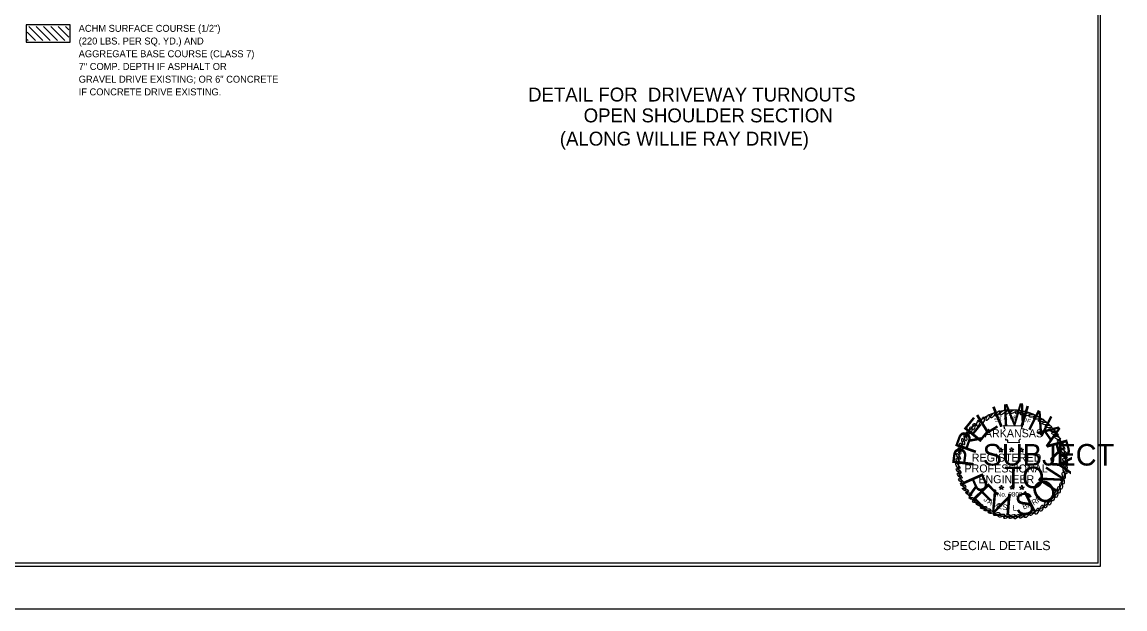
# Model space of a CAD drawing. Extents: x 714919 to 718439, y 1619644 to 1621844.
# Drawn here: x 716536 to 718439, y 1619644 to 1620657 of the extents above; entities that cross this region are included whole.
import ezdxf

# ---------------------------------------------------------------- set-up
doc = ezdxf.new("R2010")
doc.units = 0
for name, color, linetype in [('Default', 7, 'Continuous'), ('R_Border', 7, 'Continuous'), ('R_Border Notes', 7, 'Continuous'), ('R_Border PE', 7, 'Continuous'), ('R_Border Prem', 7, 'Continuous'), ('R_No Plot', 7, 'Continuous')]:
    doc.layers.add(name, color=color, linetype=linetype)

msp = doc.modelspace()

# ---------------------------------------------------------------- linework, layer by layer
at = {"layer": 'Default'}
msp.add_lwpolyline([(716543.2, 1620652), (716543.2, 1620622.1), (716619.4, 1620622.1), (716619.4, 1620652)], close=True, dxfattribs=at)
for points in [[(716545, 1620639.2), (716559.4, 1620624.9)], [(716547.7, 1620649.2), (716572.1, 1620624.9)], [(716560.4, 1620649.2), (716584.7, 1620624.9)], [(716573, 1620649.2), (716597.4, 1620624.9)], [(716585.7, 1620649.2), (716610.1, 1620624.9)], [(716598.4, 1620649.2), (716617, 1620630.6)], [(716611, 1620649.2), (716617, 1620643.3)], [(716545, 1620626.5), (716546.7, 1620624.9)]]:
    msp.add_lwpolyline(points, dxfattribs=at)
at = {"layer": 'R_Border'}
for p, q in [((718393.2, 1619722.5), (718393.1, 1621777.1)), ((718393.2, 1619722.5), (715231.2, 1619722.5)), ((714919.1, 1619643.5), (718439.3, 1619643.8))]:
    msp.add_line(p, q, dxfattribs=at)
at = {"layer": 'R_Border PE'}
for points in [[(718232.2, 1619953.8), (718230.1, 1619960.3), (718262.7, 1619959.4), (718260.3, 1619955), (718265.3, 1619954.7), (718265, 1619954.1)], [(718258.8, 1619937.5), (718256.1, 1619934.6), (718256.7, 1619930.1), (718237.2, 1619930.7), (718237.2, 1619934.9), (718233.7, 1619934.9), (718233.7, 1619937.5)]]:
    msp.add_lwpolyline(points, dxfattribs=at)
for points in [[(718225.4, 1619921.8), (718226.3, 1619918.9), (718229.2, 1619918.9), (718226.8, 1619917.4), (718227.7, 1619914.4), (718225.4, 1619916.2), (718223, 1619914.4), (718223.9, 1619917.4), (718221.5, 1619918.9), (718224.5, 1619918.9)], [(718243.7, 1619922.1), (718244.6, 1619919.5), (718247.3, 1619919.5), (718245.2, 1619917.7), (718246.1, 1619915), (718243.7, 1619916.5), (718241.3, 1619915), (718242.2, 1619917.7), (718239.9, 1619919.5), (718242.8, 1619919.5)], [(718260.6, 1619921.8), (718261.5, 1619918.9), (718264.4, 1619918.9), (718262.1, 1619917.4), (718263, 1619914.4), (718260.6, 1619916.2), (718258.2, 1619914.4), (718259.1, 1619917.4), (718256.7, 1619918.9), (718259.7, 1619918.9)], [(718226.3, 1619857), (718227.1, 1619854), (718230.1, 1619854), (718227.7, 1619852.6), (718228.6, 1619849.6), (718226.3, 1619851.4), (718223.9, 1619849.6), (718224.8, 1619852.6), (718222.4, 1619854), (718225.4, 1619854)], [(718244.6, 1619857.3), (718245.5, 1619854.6), (718248.2, 1619854.6), (718245.8, 1619852.9), (718247, 1619850.2), (718244.6, 1619851.7), (718242.2, 1619850.2), (718243.1, 1619852.9), (718240.8, 1619854.6), (718243.7, 1619854.6)], [(718261.5, 1619857), (718262.4, 1619854), (718265.3, 1619854), (718263, 1619852.6), (718263.8, 1619849.6), (718261.5, 1619851.4), (718259.1, 1619849.6), (718260, 1619852.6), (718257.6, 1619854), (718260.6, 1619854)]]:
    msp.add_lwpolyline(points, close=True, dxfattribs=at)
for centre, major_axis, ratio in [((718219.6, 1619980.9), (-3.64, -4.4), 0.329518), ((718228.4, 1619982.7), (-4.59, -4.21), 0.348728), ((718236.7, 1619983.2), (-3.87, -3.02), 0.44237), ((718246.4, 1619984.1), (-4.21, -2.45), 0.475469), ((718255.1, 1619983.2), (-4.21, -2.45), 0.475469), ((718186.2, 1619964.6), (-1.53, -5.49), 0.394697), ((718194.1, 1619969.1), (-1.53, -5.49), 0.375751), ((718202.5, 1619974), (-2.46, -5.15), 0.329518), ((718211.5, 1619978), (-3.58, -4.44), 0.329518), ((718263.2, 1619981.7), (-4.21, -2.45), 0.475469), ((718271.2, 1619979.7), (-4.64, -1.48), 0.475469), ((718278.6, 1619976.9), (-4.79, -0.89), 0.475469), ((718286.5, 1619973.3), (-4.85, -0.42), 0.475469), ((718294.8, 1619969), (-4.85, -0.42), 0.475469), ((718168.4, 1619946.2), (0, -5.7), 0.322879), ((718173.1, 1619952.2), (0, -5.7), 0.322879), ((718178.3, 1619958.3), (-1.53, -5.49), 0.391724), ((718301.4, 1619963.9), (-4.87, 0.11), 0.475469), ((718307, 1619958.6), (-5.09, 0.7), 0.451028), ((718313.3, 1619952.2), (-5.17, 1.18), 0.436264), ((718318.5, 1619945.9), (-5.3, 1.59), 0.418512), ((718156.7, 1619924.4), (1.57, -5.48), 0.322879), ((718160.2, 1619932.3), (1.57, -5.48), 0.322879), ((718164, 1619939), (1.57, -5.48), 0.322879), ((718322.8, 1619938.7), (-4.99, 2.77), 0.40589), ((718327.8, 1619930.8), (-4.66, 3.28), 0.40589), ((718151.9, 1619906.9), (3.04, -4.83), 0.322879), ((718153.5, 1619916.3), (1.57, -5.48), 0.322879), ((718330.9, 1619922.8), (-4.3, 3.75), 0.40589), ((718333.5, 1619914.9), (-4.3, 3.75), 0.40589), ((718335.2, 1619907.3), (-4.1, 3.96), 0.40589), ((718150.9, 1619890.4), (3.04, -4.83), 0.322879), ((718151.4, 1619898.8), (3.04, -4.83), 0.322879), ((718336.1, 1619898.9), (-3.5, 4.5), 0.40589), ((718336.3, 1619890.7), (-2.77, 4.99), 0.40589), ((718152.3, 1619881.7), (3.92, -4.14), 0.322879), ((718154.2, 1619873.4), (3.92, -4.14), 0.322879), ((718333.7, 1619874.3), (-1.48, 5.51), 0.40589), ((718335.8, 1619882.1), (-2.3, 5.22), 0.40589), ((718156.7, 1619864.6), (4.29, -3.76), 0.322879), ((718160.1, 1619857), (4.67, -3.27), 0.322879), ((718164.3, 1619849.4), (5.13, -2.49), 0.322879), ((718325.4, 1619849.4), (-0.33, 5.69), 0.40589), ((718329.2, 1619856.2), (-0.33, 5.69), 0.40589), ((718331.9, 1619864.8), (-1.02, 5.61), 0.40589), ((718169.6, 1619842.1), (5.13, -2.49), 0.322879), ((718175.6, 1619834.4), (5.58, -1.19), 0.322879), ((718309.7, 1619828.6), (0.91, 5.63), 0.40589), ((718315.2, 1619835.6), (0.91, 5.63), 0.40589), ((718320.9, 1619841.8), (0.27, 5.7), 0.40589), ((718181.3, 1619828.6), (5.58, -1.19), 0.322879), ((718188.3, 1619823.6), (5.58, -1.19), 0.322879), ((718195.1, 1619818.5), (5.68, 0.48), 0.322879), ((718201.8, 1619814.6), (5.68, 0.48), 0.322879), ((718279, 1619809.5), (3.39, 4.59), 0.40589), ((718287.4, 1619812.2), (2.43, 5.16), 0.40589), ((718295.4, 1619817.3), (2.26, 5.24), 0.40589), ((718302.8, 1619823.7), (1.36, 5.54), 0.40589), ((718209, 1619810.8), (5.68, 0.48), 0.40589), ((718218, 1619807.3), (5.5, 1.52), 0.40589), ((718226.3, 1619804.7), (5.5, 1.52), 0.40589), ((718235.5, 1619803.3), (4.91, 2.91), 0.40589), ((718244.7, 1619803.2), (4.91, 2.91), 0.40589), ((718252.8, 1619803.1), (4.63, 3.33), 0.40589), ((718261.9, 1619804.4), (4.36, 3.68), 0.40589), ((718270.3, 1619805.7), (4.08, 3.98), 0.40589)]:
    msp.add_ellipse(centre, major_axis=major_axis, ratio=ratio, dxfattribs=at)
at = {"layer": 'R_Border Prem'}
msp.add_circle((718244.5, 1619894.9), 92.6, dxfattribs=at)
at = {"layer": 'R_No Plot'}
msp.add_lwpolyline([(715227.2, 1619717.3), (718397.1, 1619717.4), (718397.2, 1621782.5), (715227.1, 1621782.3)], close=True, dxfattribs=at)

# ---------------------------------------------------------------- texts
at = {"layer": 'Default'}
for s, height, p in [('ACHM SURFACE COURSE (1/2") ', 12, (716634, 1620639.9)), ('(220 LBS. PER SQ. YD.) AND ', 12, (716634, 1620618)), ('AGGREGATE BASE COURSE (CLASS 7)', 12, (716634, 1620596)), ('7" COMP. DEPTH IF ASPHALT OR', 12, (716634, 1620574.1)), ('GRAVEL DRIVE EXISTING; OR 6" CONCRETE', 12, (716634, 1620552.1)), ('IF CONCRETE DRIVE EXISTING.', 12, (716634, 1620530.2)), ('DETAIL FOR  DRIVEWAY TURNOUTS', 24, (717409.4, 1620519.6)), ('OPEN SHOULDER SECTION', 24, (717505.3, 1620483.6)), ('(ALONG WILLIE RAY DRIVE)', 24, (717464.2, 1620443.5))]:
    msp.add_text(s, height=height, dxfattribs=at).set_placement(p)
at = {"layer": 'R_Border Notes'}
msp.add_text('SPECIAL DETAILS', height=16, rotation=359.9984, dxfattribs=at).set_placement((718125.4, 1619745.1))
at = {"layer": 'R_Border PE'}
for s, height, rotation, p in [('S', 6.91, 19.5814, (718215.3, 1619965.6)), ('T', 6.91, 14.9614, (718222.7, 1619968)), ('A', 6.91, 5.7216, (718230.1, 1619969.8)), ('T', 6.91, 1.1017, (718238.4, 1619970.4)), ('E', 6.91, 356.4818, (718246.4, 1619970.4)), ('O', 6.91, 342.6221, (718261.8, 1619968.3)), ('F', 6.91, 338.0022, (718269.5, 1619965.9)), ('ARKANSAS', 13.81, 360, (718197.5, 1619939.9)), ('REGISTERED', 13.81, 360, (718175, 1619897.9)), ('PROFESSIONAL', 13.814, 360, (718162.3, 1619879.2)), ('ENGINEER', 13.81, 360, (718186.3, 1619860.6)), ('J', 9.6, 322.4167, (718194.5, 1619831.2)), ('No. 9808', 7.89, 360, (718218.1, 1619837.5)), ('R', 9.6, 29.6215, (718281.7, 1619822)), ('R', 9.6, 35.2219, (718289.6, 1619826.8)), ('A', 9.6, 328.0171, (718201, 1619826.4)), ('M', 9.6, 333.6175, (718209.3, 1619821.6)), ('E', 9.6, 344.8183, (718218.8, 1619817.5)), ('S', 9.6, 350.4187, (718227.2, 1619815.1)), ('L', 9.6, 1.6195, (718245.5, 1619813.2)), ('.', 9.6, 7.2199, (718254.4, 1619813.8)), ('B', 9.6, 18.4207, (718264.1, 1619815.3)), ('A', 9.6, 24.0211, (718272.9, 1619818))]:
    msp.add_text(s, height=height, rotation=rotation, dxfattribs=at).set_placement(p)
at = {"layer": 'R_Border Prem'}
for s, height, rotation, p in [('I', 37.2, 22.0105, (718219.9, 1619955.5)), ('M', 37.2, 2.6943, (718228, 1619959.6)), ('I', 37.2, 343.3781, (718254.3, 1619960.2)), ('N', 37.2, 333.7199, (718268.9, 1619955.7)), ('E', 37.2, 50.9849, (718187.3, 1619928.3)), ('L', 37.2, 31.6686, (718198.3, 1619943.3)), ('R', 37.2, 70.3011, (718179.9, 1619908.7)), ('A', 37.2, 304.7456, (718286.4, 1619949.1)), ('SUBJECT', 37.24, 360, (718193.8, 1619891.1)), ('R', 37.2, 285.4294, (718302.5, 1619930.3)), ('P', 37.2, 82.6089, (718177.4, 1619887)), ('Y', 37.2, 266.1131, (718311.1, 1619910.3)), ('R', 37.2, 293.7639, (718158.1, 1619866.7)), ('TO', 37.24, 360, (718231.4, 1619852)), ('N', 37.2, 57.1378, (718318.1, 1619842.4)), ('E', 37.2, 314.3262, (718174.1, 1619837.5)), ('O', 37.2, 36.5754, (718295.4, 1619820.2)), ('V', 37.2, 334.8885, (718197.2, 1619817.2)), ('I', 37.2, 355.4508, (718230, 1619805.4)), ('S', 37.2, 5.732, (718251.5, 1619804.8)), ('I', 37.2, 26.2943, (718276.5, 1619809.9))]:
    msp.add_text(s, height=height, rotation=rotation, dxfattribs=at).set_placement(p)

doc.saveas('drawing.dxf')
